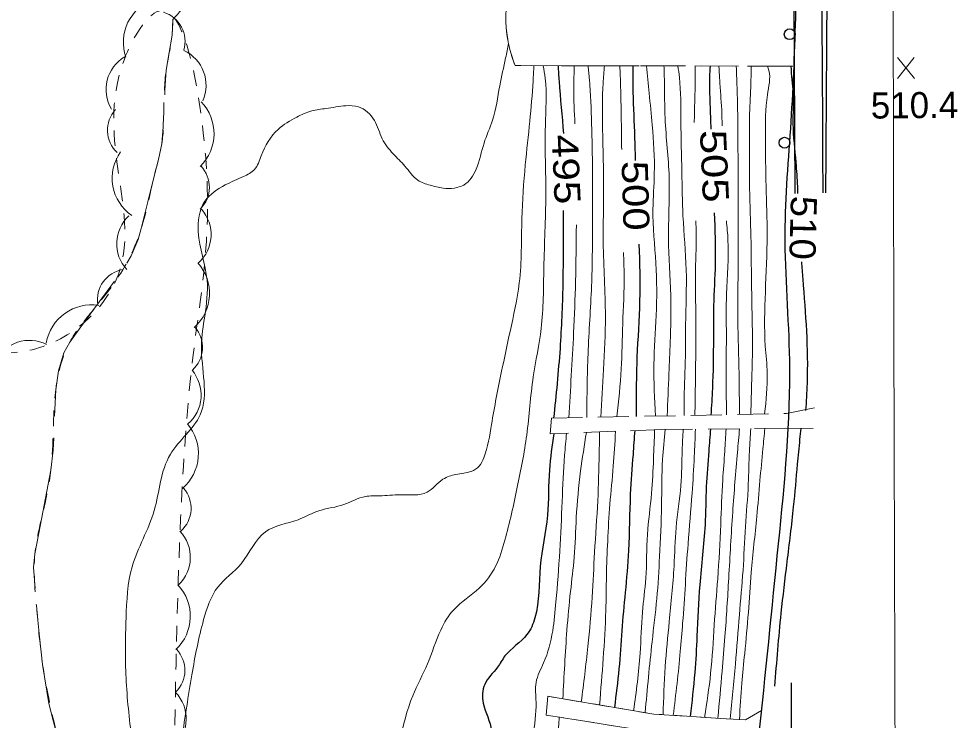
# Model space of a CAD drawing. Extents: x 2362213 to 2366494, y 6968794 to 6978110.
# Drawn here: x 2364222.2 to 2364394.8, y 6970115.9 to 6970244.9 of the extents above; entities that cross this region are included whole.
import ezdxf
from ezdxf.enums import TextEntityAlignment as Align

# ---------------------------------------------------------------- set-up
doc = ezdxf.new("R2010")
doc.units = 0
doc.header["$LTSCALE"] = 1.9
doc.linetypes.add('MEDIUM_DASHED', pattern=[4.5, 3, -1.5])
doc.linetypes.add('SHORT_DASHED', pattern=[2.7, 1.5, -1.2])
for name, color, linetype, lineweight in [('2', 7, 'Continuous', 25), ('28', 7, 'Continuous', 13), ('29', 7, 'Continuous', 13), ('31', 7, 'Continuous', 25), ('35', 7, 'Continuous', 13), ('36', 7, 'Continuous', 13), ('4', 7, 'Continuous', 25), ('62', 7, 'Continuous', 13), ('8', 7, 'Continuous', 13)]:
    doc.layers.add(name, color=color, linetype=linetype, lineweight=lineweight)

msp = doc.modelspace()

# ---------------------------------------------------------------- linework, layer by layer
at = {"layer": '2'}
for centre, radius, start, end in [((2348841.903, 6970149.815), 15528.336, 0.23277, 0.37177), ((2348832.824, 6970339.444), 15538.302, 359.53334, 359.67224)]:
    msp.add_arc(centre, radius, start, end, dxfattribs=at)
at = {"layer": '28', "linetype": 'MEDIUM_DASHED'}
for p, q in [((2364363.376, 6970172.302), (2364368.558, 6970173.361)), ((2364368.314, 6970169.53), (2364363.212, 6970169.581))]:
    msp.add_line(p, q, dxfattribs=at)
at = {"layer": '28'}
for p, q in [((2364322.676, 6970119.763), (2364330.568, 6970118.438)), ((2364342.435, 6970116.801), (2364350.42, 6970116.297)), ((2364332.313, 6970114.755), (2364324.412, 6970116))]:
    msp.add_line(p, q, dxfattribs=at)
at = {"layer": '28', "linetype": 'MEDIUM_DASHED'}
for points in [[(2364363.212, 6970169.581), (2364340.373, 6970169.374), (2364319.911, 6970168.549), (2364320.154, 6970171.46), (2364363.376, 6970172.302)], [(2364358.012, 6970110.818), (2364336.369, 6970114.113), (2364319.193, 6970116.83), (2364319.49, 6970120.303), (2364339.012, 6970117.019), (2364355.863, 6970115.949), (2364358.816, 6970117.707)]]:
    msp.add_lwpolyline(points, dxfattribs=at)
at = {"layer": '28'}
for points in [[(2364322.439, 6970116.311), (2364319.193, 6970116.83), (2364319.49, 6970120.303), (2364320.703, 6970120.094)], [(2364332.541, 6970118.107), (2364339.012, 6970117.019), (2364340.443, 6970116.932)], [(2364352.412, 6970116.166), (2364355.863, 6970115.949), (2364358.816, 6970117.707)]]:
    msp.add_lwpolyline(points, dxfattribs=at)
at = {"layer": '29'}
for centre, radius, start, end in [((2364249.865, 6970240.562), 8.404, 108.9429, 198.9429), ((2364247.218, 6970240.738), 5.599, 343.21997, 73.21997), ((2364245.288, 6970231.884), 7.006, 120.67083, 210.67083), ((2364249.665, 6970232.701), 7.006, 335.61376, 65.61376), ((2364249.727, 6970223.78), 8.404, 314.31165, 44.31165), ((2364244.14, 6970224.415), 5.599, 137.44999, 227.44999), ((2364247.813, 6970215.607), 8.404, 144.99496, 234.99496), ((2364251.68, 6970213.925), 5.599, 314.31165, 44.31165), ((2364247.244, 6970203.539), 7.006, 132.81249, 222.81249), ((2364250.585, 6970205.216), 7.006, 311.79145, 41.79145), ((2364248.896, 6970194.393), 8.404, 311.79145, 41.79145), ((2364242.3, 6970193.258), 5.599, 99.27283, 189.27283), ((2364235.594, 6970183.891), 8.404, 80.66437, 170.66437), ((2364250.414, 6970184.462), 5.599, 311.79145, 41.79145), ((2364224.218, 6970178.757), 7.006, 63.54578, 153.54578), ((2364248.771, 6970175.704), 7.006, 310.61614, 40.61614), ((2364246.861, 6970164.918), 8.404, 310.61614, 40.61614), ((2364248.316, 6970154.889), 5.599, 311.46406, 41.46406), ((2364246.77, 6970145.872), 7.006, 313.27949, 43.27949), ((2364245.363, 6970135.009), 8.404, 313.27949, 43.27949), ((2364247.175, 6970125.076), 5.599, 313.91426, 43.91426), ((2364246.015, 6970116.158), 7.006, 313.91426, 43.91426)]:
    msp.add_arc(centre, radius, start, end, dxfattribs=at)
at = {"layer": '29', "linetype": 'SHORT_DASHED'}
msp.add_spline([(2363819.747, 6970158.026), (2363833.428, 6970176.986), (2363859.818, 6970191.748), (2363889.175, 6970213.148), (2363902.004, 6970241.742), (2363923.176, 6970262.634), (2363951.045, 6970272.321), (2363972.181, 6970282.342), (2363989.376, 6970285.026), (2364009.131, 6970284.544), (2364040.025, 6970289.639), (2364067.833, 6970297.314), (2364089.729, 6970309.363), (2364116.874, 6970334.123), (2364142.838, 6970357.901), (2364162.086, 6970364.585), (2364191.414, 6970361.824), (2364204.329, 6970351.877), (2364204.017, 6970346.834), (2364196.865, 6970314.464), (2364198.103, 6970273.714), (2364205.818, 6970229.125), (2364210.955, 6970185.492), (2364223.99, 6970183.886), (2364240.264, 6970197.181), (2364241.582, 6970237.316), (2364247.956, 6970246.327), (2364255.782, 6970226.971), (2364254.29, 6970183.115), (2364251.704, 6970145.778), (2364250.854, 6970111.088)], degree=3, dxfattribs=at)
at = {"layer": '31', "lineweight": 13}
for p, q in [((2364386.892, 6970233.93), (2364383.774, 6970237.78)), ((2364383.811, 6970233.9), (2364386.855, 6970237.81))]:
    msp.add_line(p, q, dxfattribs=at)
at = {"layer": '31'}
for points in [[(2364321.376, 6970236.276), (2364321.564, 6970233.428), (2364322.405, 6970223.795)], [(2364335.116, 6970236.247), (2364335.142, 6970232.467), (2364335.412, 6970224.109), (2364335.592, 6970218.86)], [(2364349.328, 6970236.222), (2364349.238, 6970234.181), (2364349.314, 6970229.262), (2364349.469, 6970224.593)], [(2364364.199, 6970236.194), (2364364.363, 6970233.655), (2364364.566, 6970231.317), (2364364.57, 6970225.607), (2364365.098, 6970218.481), (2364365.39, 6970214.044), (2364365.432, 6970212.794)], [(2364322.31, 6970209.624), (2364322.25, 6970195.972), (2364321.742, 6970184.257), (2364320.574, 6970171.464)], [(2364350.115, 6970209.228), (2364350.275, 6970199.84), (2364349.978, 6970192.126), (2364349.936, 6970186.066), (2364349.763, 6970176.913), (2364349.489, 6970172.03)], [(2364336.249, 6970203.446), (2364336.388, 6970193.046), (2364335.887, 6970182.652), (2364335.77, 6970171.769)], [(2364366.122, 6970200.23), (2364366.372, 6970197.062), (2364367.165, 6970177.849), (2364366.893, 6970172.836)], [(2364320.631, 6970168.576), (2364319.783, 6970161.938), (2364319.423, 6970153.593), (2364318.092, 6970144.171), (2364317.132, 6970134.701), (2364315.671, 6970131.646), (2364311.629, 6970127.717), (2364310.238, 6970125.634), (2364307.898, 6970122.483), (2364307.641, 6970119.04), (2364309.109, 6970113.974), (2364309.084, 6970112.483)], [(2364335.475, 6970169.177), (2364335.167, 6970164.784), (2364334.667, 6970157.449), (2364334.345, 6970147.085), (2364333.729, 6970139.379), (2364333.105, 6970132.362), (2364332.582, 6970125.347), (2364331.74, 6970118.239)], [(2364349.414, 6970169.46), (2364349.083, 6970165.377), (2364348.645, 6970158.852), (2364348.402, 6970151.819), (2364347.427, 6970140.79), (2364346.927, 6970131.364), (2364346.52, 6970124.659), (2364345.667, 6970116.592)], [(2364366.004, 6970169.558), (2364365.803, 6970167.556), (2364365.366, 6970162.972), (2364364.641, 6970155.163), (2364363.446, 6970145.003), (2364362.356, 6970135.572), (2364361.184, 6970122.13)], [(2364364.269, 6970122.769), (2364364.217, 6970120.849), (2364364.104, 6970112.737), (2364363.964, 6970111.696)]]:
    msp.add_spline(points, degree=3, dxfattribs=at)
at = {"layer": '35'}
for points in [[(2364364.934, 6970331.275), (2364362.144, 6970330.109), (2364357.699, 6970327.476), (2364355.669, 6970326.367), (2364352.328, 6970324.385), (2364349.035, 6970321.583), (2364345.467, 6970317.179), (2364341.517, 6970311.781), (2364336.606, 6970308.744), (2364330.172, 6970303.853), (2364324.058, 6970301.205), (2364317.825, 6970299.335), (2364310.241, 6970294.473), (2364303.2, 6970286.224), (2364298.569, 6970283.181), (2364292.843, 6970282.646), (2364287.566, 6970282.236), (2364280.435, 6970280.298), (2364271.242, 6970276.33), (2364264.589, 6970268.207), (2364258.256, 6970261.216), (2364256.007, 6970252.664), (2364250.581, 6970244.802)], [(2364312.266, 6970240.378), (2364311.751, 6970237.704), (2364310.67, 6970232.584), (2364309.34, 6970226.261), (2364307.77, 6970222.036), (2364306.316, 6970217.241), (2364304.055, 6970214.33), (2364302.33, 6970213.764), (2364300.27, 6970213.764), (2364297.855, 6970214.301), (2364295.625, 6970215.21), (2364293.24, 6970217.806), (2364291.058, 6970220.076), (2364289.062, 6970222.818), (2364287.61, 6970226.214), (2364284.706, 6970228.717), (2364282.375, 6970228.904), (2364278.709, 6970228.409), (2364276.113, 6970227.975), (2364273.353, 6970226.818), (2364269.905, 6970224.565), (2364266.811, 6970219.725), (2364265.575, 6970217.193), (2364263.577, 6970215.904), (2364260.211, 6970214.353), (2364256.461, 6970211.347), (2364255.214, 6970205.715), (2364256.859, 6970196.819), (2364256.422, 6970190.215), (2364255.814, 6970184.799), (2364255.585, 6970172.066), (2364250.103, 6970164.804), (2364247.131, 6970154.464), (2364243.089, 6970144.126), (2364241.959, 6970134.655), (2364241.954, 6970123.654), (2364243.001, 6970112.444)], [(2364316.935, 6970236.284), (2364316.792, 6970233.452), (2364316.192, 6970226.096), (2364315.359, 6970218.047), (2364314.733, 6970208.142), (2364314.256, 6970196.325), (2364312.551, 6970187.36), (2364311.01, 6970180.065), (2364309.143, 6970170.316), (2364307.741, 6970164.163), (2364306.856, 6970162.594), (2364305.426, 6970161.671), (2364302.621, 6970161.104), (2364300.23, 6970160.211), (2364297.321, 6970157.843), (2364292.396, 6970157.357), (2364288.557, 6970157.17), (2364285.978, 6970157.055), (2364281.993, 6970155.557), (2364277.564, 6970154.454), (2364273.578, 6970152.776), (2364267.579, 6970150.549), (2364263.125, 6970144.687), (2364258.837, 6970140.376), (2364256.223, 6970134.411), (2364254.06, 6970124.239), (2364252.23, 6970112.642)], [(2364318.645, 6970236.28), (2364319.007, 6970233.973), (2364319.05, 6970225.233), (2364319.132, 6970212.514), (2364318.769, 6970199.089), (2364318.285, 6970187.964), (2364316.82, 6970179.03), (2364315.622, 6970168.348), (2364313.893, 6970158.761), (2364311.606, 6970148.988), (2364309.911, 6970144.243), (2364306.91, 6970140.204), (2364302.218, 6970136.229), (2364299.824, 6970132.475), (2364297.372, 6970126.261), (2364294.668, 6970120.396), (2364292.286, 6970112.123)], [(2364324.367, 6970236.265), (2364324.276, 6970232.183), (2364324.488, 6970225.575)], [(2364326.907, 6970236.269), (2364327.151, 6970233.761), (2364327.558, 6970225.594), (2364327.72, 6970216.995), (2364327.724, 6970207.135), (2364327.542, 6970195.792), (2364326.892, 6970183.246), (2364326.663, 6970171.582)], [(2364329.896, 6970236.257), (2364329.666, 6970233.075), (2364329.563, 6970224.974), (2364329.769, 6970213.855), (2364329.695, 6970203.794), (2364330.094, 6970190.207), (2364329.758, 6970180.393), (2364329.252, 6970171.637)], [(2364332.746, 6970236.254), (2364332.882, 6970232.445), (2364333.02, 6970225.376), (2364333.083, 6970220.836)], [(2364337.656, 6970236.241), (2364338.134, 6970231.215), (2364338.7, 6970225.381), (2364339.085, 6970216.423), (2364338.827, 6970209.891), (2364339.352, 6970199.956), (2364339.444, 6970190.326), (2364338.999, 6970181.331), (2364339.32, 6970171.833)], [(2364340.857, 6970236.232), (2364340.933, 6970233.522), (2364341.068, 6970226.623), (2364341.812, 6970215.74), (2364341.691, 6970204.248), (2364342.123, 6970193.681), (2364342.01, 6970185.47), (2364341.775, 6970179.668), (2364341.44, 6970171.873)], [(2364343.418, 6970236.236), (2364343.698, 6970234.129), (2364343.975, 6970226.071), (2364344.144, 6970216.731), (2364344.35, 6970208.654), (2364344.945, 6970198.738), (2364344.841, 6970188.647), (2364344.776, 6970181.856), (2364344.603, 6970176.924), (2364344.59, 6970171.933)], [(2364346.568, 6970236.226), (2364346.588, 6970233.116), (2364346.462, 6970227.415), (2364346.427, 6970225.834)], [(2364350.958, 6970236.218), (2364351.08, 6970233.979), (2364351.288, 6970231.041), (2364351.543, 6970225.253), (2364351.543, 6970225.243)], [(2364354.158, 6970236.208), (2364354.239, 6970233.929), (2364354.432, 6970226.34), (2364354.474, 6970215.54), (2364354.525, 6970202.9), (2364354.442, 6970189.499), (2364354.656, 6970179.64), (2364354.748, 6970172.13)], [(2364356.898, 6970236.204), (2364356.867, 6970234.194), (2364356.748, 6970230.923), (2364356.561, 6970225.391), (2364356.588, 6970219.37), (2364356.602, 6970213.69), (2364356.848, 6970204.662), (2364356.923, 6970198.842), (2364357.031, 6970191.744), (2364357.121, 6970183.384), (2364356.987, 6970178.513), (2364356.837, 6970172.17)], [(2364359.888, 6970236.203), (2364360.145, 6970235.405), (2364359.878, 6970230.922), (2364359.512, 6970223.199), (2364359.628, 6970214.109), (2364359.824, 6970205.121), (2364359.494, 6970194.646), (2364359.488, 6970184.707), (2364359.846, 6970179.74), (2364359.367, 6970172.224)], [(2364324.755, 6970206.997), (2364324.604, 6970196.624), (2364324.245, 6970187.131), (2364323.343, 6970171.521)], [(2364346.699, 6970207.766), (2364346.773, 6970206.337), (2364346.646, 6970198.614), (2364346.698, 6970191.085), (2364346.695, 6970182.975), (2364346.54, 6970171.972)], [(2364352.33, 6970207.74), (2364352.622, 6970204.252), (2364352.348, 6970194.268), (2364352.329, 6970186.749), (2364352.289, 6970180.518), (2364352.359, 6970172.087)], [(2364333.413, 6970201.899), (2364333.532, 6970197.849), (2364333.278, 6970188.767), (2364332.997, 6970180.494), (2364332.221, 6970171.695)], [(2364322.94, 6970168.668), (2364322.589, 6970164.624), (2364322.129, 6970156.15), (2364321.706, 6970147.034), (2364320.995, 6970137.658), (2364320.396, 6970132.321), (2364318.731, 6970126.455), (2364317.345, 6970122.853), (2364317.34, 6970119.242), (2364316.74, 6970112.946), (2364316.636, 6970112.295)], [(2364326.599, 6970168.823), (2364325.526, 6970161.742), (2364324.738, 6970153.163), (2364324.347, 6970145.87), (2364323.677, 6970139.594), (2364323.015, 6970132.476), (2364322.275, 6970119.839)], [(2364329.018, 6970168.916), (2364328.946, 6970164.965), (2364328.679, 6970156.272), (2364328.099, 6970146.785), (2364327.647, 6970138.541), (2364326.874, 6970129.483), (2364325.661, 6970119.262)], [(2364331.946, 6970169.034), (2364331.537, 6970162.609), (2364330.913, 6970155.663), (2364330.509, 6970148.818), (2364330.279, 6970142.457), (2364330.17, 6970136.095), (2364329.685, 6970127.259), (2364329.026, 6970118.694)], [(2364339.134, 6970169.322), (2364338.935, 6970163.96), (2364338.575, 6970157.626), (2364337.827, 6970150.068), (2364337.514, 6970141.995), (2364336.913, 6970135.789), (2364336.475, 6970128.214), (2364335.276, 6970117.643)], [(2364341.083, 6970169.381), (2364340.606, 6970163.866), (2364340.416, 6970155.443), (2364340.056, 6970146.02), (2364339.539, 6970138.275), (2364338.675, 6970130.325), (2364337.399, 6970117.293)], [(2364344.384, 6970169.412), (2364344.211, 6970165.55), (2364343.953, 6970159.078), (2364343.096, 6970151.308), (2364342.704, 6970144.255), (2364341.83, 6970134.046), (2364341.089, 6970125.718), (2364340.693, 6970116.915)], [(2364346.634, 6970169.434), (2364346.432, 6970164.391), (2364346.026, 6970157.687), (2364345.285, 6970148.309), (2364344.786, 6970140.875), (2364344.294, 6970133.76), (2364343.864, 6970128.514), (2364342.575, 6970116.792)], [(2364352.264, 6970169.477), (2364352.043, 6970165.385), (2364351.653, 6970160.101), (2364351.291, 6970151.896), (2364350.736, 6970141.921), (2364350.097, 6970133.415), (2364349.442, 6970124.527), (2364348.309, 6970116.427)], [(2364354.753, 6970169.501), (2364354.364, 6970165.197), (2364353.499, 6970154.157), (2364352.765, 6970142.031), (2364352.077, 6970131.323), (2364351.548, 6970124.937), (2364350.78, 6970116.271)], [(2364356.813, 6970169.52), (2364356.562, 6970165.368), (2364356.36, 6970159.346), (2364355.835, 6970151.459), (2364355.391, 6970143.466), (2364354.719, 6970135.279), (2364353.985, 6970126.211), (2364353.002, 6970116.132)], [(2364359.413, 6970169.545), (2364359.048, 6970165.802), (2364358.504, 6970159.966), (2364357.927, 6970153.369), (2364356.905, 6970143.07), (2364356.375, 6970135.705), (2364355.696, 6970128.177), (2364355.159, 6970122.693), (2364354.732, 6970116.018)], [(2364321.607, 6970116.453), (2364321.474, 6970114.681), (2364320.781, 6970109.754), (2364319.737, 6970101.703), (2364318.954, 6970091.486), (2364317.664, 6970079.893), (2364316.76, 6970075.075), (2364313.998, 6970061.597), (2364311.538, 6970051.104), (2364308.601, 6970042.395), (2364306.813, 6970034.957), (2364305.456, 6970024.085), (2364301.449, 6970017.455), (2364298.418, 6970015.466), (2364295.042, 6970013.834), (2364293.263, 6970010.637), (2364291.191, 6970006.647), (2364289.816, 6969997.664), (2364290.575, 6969992.561), (2364291.255, 6969985.137), (2364289.414, 6969979.02), (2364287.697, 6969973.412), (2364285.062, 6969964.567), (2364280.792, 6969951.956), (2364277.813, 6969941.367), (2364275.206, 6969930.392), (2364271.602, 6969915.047), (2364269.476, 6969902.016), (2364265.943, 6969883.361), (2364263.955, 6969868.512), (2364263.177, 6969856.694), (2364262.701, 6969842.718), (2364260.684, 6969835.099), (2364256.935, 6969827.563)]]:
    msp.add_spline(points, degree=3, dxfattribs=at)
at = {"layer": '36'}
for points in [[(2364250.581, 6970244.802), (2364250.515, 6970243.341), (2364250.409, 6970241.89), (2364249.869, 6970238.684), (2364249.35, 6970235.48), (2364249.115, 6970231.798), (2364249.063, 6970230.907)], [(2364248.841, 6970226.915), (2364248.769, 6970225.024), (2364248.539, 6970221.932), (2364247.936, 6970219.045), (2364247.183, 6970216.198), (2364245.99, 6970211.257), (2364244.757, 6970206.325), (2364244.156, 6970204.289), (2364242.925, 6970201.337), (2364242.088, 6970199.949)], [(2364239.839, 6970196.647), (2364238.477, 6970194.804), (2364235.664, 6970191.008), (2364233.63, 6970188.238), (2364231.606, 6970185.439), (2364230.514, 6970183.438), (2364229.546, 6970180.129), (2364229.039, 6970176.683), (2364228.815, 6970171.801)], [(2364228.653, 6970167.81), (2364228.575, 6970165.549), (2364228.14, 6970161.875), (2364227.416, 6970158.018), (2364226.683, 6970154.16), (2364225.94, 6970150.322), (2364225.206, 6970146.485), (2364224.96, 6970143.974), (2364225.257, 6970140.136)], [(2364225.565, 6970136.149), (2364226.041, 6970131.232), (2364226.62, 6970126.138), (2364227.738, 6970118.999), (2364229.545, 6970112.006)]]:
    msp.add_lwpolyline(points, dxfattribs=at)
at = {"layer": '36', "linetype": 'SHORT_DASHED'}
msp.add_spline([(2364250.581, 6970244.802), (2364250.409, 6970241.89), (2364249.35, 6970235.48), (2364248.89, 6970228.115), (2364248.539, 6970221.932), (2364247.183, 6970216.198), (2364244.757, 6970206.325), (2364241.28, 6970198.611), (2364235.664, 6970191.008), (2364231.606, 6970185.439), (2364229.039, 6970176.683), (2364228.14, 6970161.875), (2364226.683, 6970154.16), (2364225.206, 6970146.485), (2364225.543, 6970136.339), (2364226.62, 6970126.138), (2364229.545, 6970112.006)], degree=3, dxfattribs=at)
at = {"layer": '4'}
msp.add_line((2364359.347, 6971077.993), (2364364.943, 6970212.75), dxfattribs=at)
for centre in [(2364363.977, 6970242.064), (2364363.024, 6970222.107)]:
    msp.add_circle(centre, 1, dxfattribs=at)
msp.add_spline([(2364358.277, 6970112.342), (2364361.924, 6970148.357), (2364363.973, 6970182.139), (2364363.141, 6970205.392), (2364364.236, 6970226.034), (2364365.123, 6970246.333), (2364364.832, 6970375.556), (2364364.876, 6970504.322), (2364364.587, 6970660.737), (2364364.458, 6970830.654), (2364364.317, 6970921.087), (2364363.346, 6970944.209), (2364361.189, 6970974.401), (2364360.625, 6971005.267), (2364359.468, 6971054.297), (2364359.925, 6971077.632)], degree=3, dxfattribs=at)
at = {"layer": '62'}
msp.add_spline([(2364383.348, 6970112.421), (2364382.992, 6970277.885), (2364383.14, 6970438.813), (2364382.733, 6970634.828), (2364382.506, 6970838.246), (2364381.952, 6970986.738), (2364381.794, 6971076.85)], degree=3, dxfattribs=at)
at = {"layer": '8', "linetype": 'MEDIUM_DASHED'}
msp.add_line((2364313.485, 6970236.291), (2364364.679, 6970236.188), dxfattribs=at)
at = {"layer": '8'}
for p, q in [((2364316.545, 6970236.29), (2364324.547, 6970236.276)), ((2364326.547, 6970236.275), (2364334.546, 6970236.261)), ((2364336.546, 6970236.261), (2364344.548, 6970236.237)), ((2364346.548, 6970236.236), (2364354.548, 6970236.212)), ((2364356.548, 6970236.211), (2364364.549, 6970236.187))]:
    msp.add_line(p, q, dxfattribs=at)
msp.add_lwpolyline([(2364311.881, 6970243.015), (2364311.903, 6970242.735), (2364311.947, 6970242.326), (2364312.001, 6970241.906), (2364312.065, 6970241.497), (2364312.129, 6970241.087), (2364312.203, 6970240.688), (2364312.287, 6970240.279), (2364312.371, 6970239.869), (2364312.465, 6970239.47), (2364312.568, 6970239.071), (2364312.682, 6970238.663), (2364312.796, 6970238.264), (2364312.92, 6970237.876), (2364313.044, 6970237.477), (2364313.187, 6970237.088), (2364313.331, 6970236.699), (2364313.475, 6970236.311), (2364313.485, 6970236.291), (2364314.545, 6970236.291)], dxfattribs=at)
at = {"layer": '8', "linetype": 'MEDIUM_DASHED'}
msp.add_arc((2364335.536, 6970245.104), 23.746, 155.72745, 201.78572, dxfattribs=at)

# ---------------------------------------------------------------- texts
at = {"layer": '31'}
msp.add_text('510.4', height=4.8, rotation=0.546, dxfattribs=at).set_placement((2364378.911, 6970226.543))
for s, rotation, width, p in [(' 505 ', 272.473, 1.25, (2364347.753, 6970217.703)), (' 495 ', 272.402, 1.2, (2364320.497, 6970217.132)), (' 500 ', 271.61, 1.2, (2364333.248, 6970212.302)), (' 510 ', 268.551, 1.1, (2364364.055, 6970206.524))]:
    msp.add_text(s, height=4.8, rotation=rotation, dxfattribs=dict(at, width=width)).set_placement(p, align=Align.CENTER)

doc.saveas('drawing.dxf')
